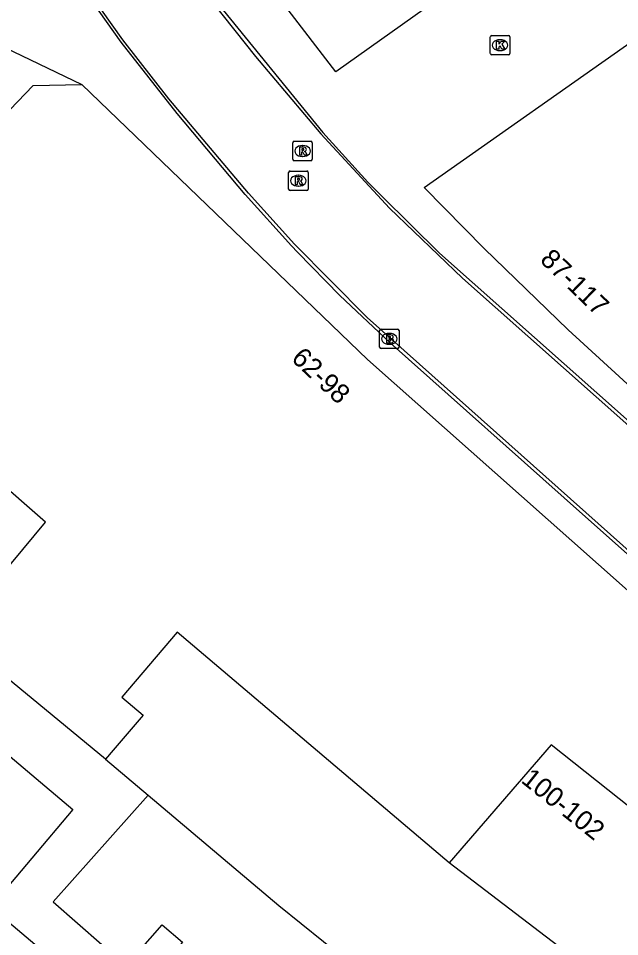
# Model space of a CAD drawing. Extents: x 161087 to 161922, y 382574 to 383873.
# Drawn here: x 161162.7 to 161193.61, y 383299.11 to 383346.31 of the extents above; entities that cross this region are included whole.
import ezdxf

# ---------------------------------------------------------------- set-up
doc = ezdxf.new("R2010")
doc.units = 0
for name, color, linetype in [('IMGEO_Brandkraan', 7, 'Continuous'), ('IMGEO_Kolk', 7, 'Continuous'), ('IMGEO_Lijnafwatering', 7, 'Continuous'), ('IMGEO_Pand', 7, 'Continuous'), ('IMGEO_Pand_nummerreeks', 7, 'Continuous'), ('IMGEO_Rioolput', 7, 'Continuous'), ('IMGEO_Voetgangersgebied_open', 7, 'Continuous')]:
    doc.layers.add(name, color=color, linetype=linetype)

msp = doc.modelspace()

# ---------------------------------------------------------------- linework, layer by layer
at = {"layer": 'IMGEO_Brandkraan'}
for p, q in [((161181.267, 383329.408), (161181.267, 383330.26)), ((161181.342, 383330.334), (161182.194, 383330.334)), ((161182.268, 383330.26), (161182.268, 383329.408)), ((161181.755, 383330.114), (161181.78, 383330.114)), ((161182.194, 383329.334), (161181.342, 383329.334)), ((161181.778, 383329.554), (161181.753, 383329.554))]:
    msp.add_line(p, q, dxfattribs=at)
for points in [[(161181.267, 383329.408), (161181.267, 383330.26)], [(161181.342, 383330.334), (161182.194, 383330.334)], [(161182.268, 383330.26), (161182.268, 383329.408)], [(161181.615, 383330.034), (161181.615, 383329.634), (161181.828, 383329.634)], [(161181.846, 383330.034), (161181.615, 383330.034)], [(161181.794, 383329.953), (161181.74, 383329.953), (161181.74, 383329.877)], [(161181.74, 383329.877), (161181.793, 383329.877)], [(161181.802, 383329.801), (161181.74, 383329.801), (161181.74, 383329.72)], [(161182.194, 383329.334), (161181.342, 383329.334)], [(161181.74, 383329.72), (161181.802, 383329.72)]]:
    msp.add_lwpolyline(points, dxfattribs=at)
for centre, radius, start, end in [((161181.344, 383330.258), 0.0765, 91.552, 178.448), ((161181.344, 383330.258), 0.0765, 91.552, 178.448), ((161182.192, 383330.258), 0.0765, 1.552, 88.448), ((161182.192, 383330.258), 0.0765, 1.552, 88.448), ((161181.795, 383329.915), 0.0379, 267.8285, 90.9355), ((161181.803, 383329.76), 0.0404, 269.8759, 90.5077), ((161181.85, 383329.889), 0.145, 59.4692, 91.5367), ((161181.875, 383329.936), 0.0922, 285.5137, 58.1501), ((161181.88, 383329.744), 0.105, 301.3115, 78.989), ((161181.344, 383329.41), 0.0765, 181.552, 268.448), ((161181.344, 383329.41), 0.0765, 181.552, 268.448), ((161181.834, 383329.885), 0.251, 268.6676, 293.5347), ((161182.192, 383329.41), 0.0765, 271.552, 358.448), ((161182.192, 383329.41), 0.0765, 271.552, 358.448)]:
    msp.add_arc(centre, radius, start, end, dxfattribs=at)
for centre, major_axis, ratio, start_param, end_param in [((161181.754, 383329.834), (-0.387, 0.002), 0.722429, 4.712389, 7.853982), ((161181.779, 383329.834), (-0.39, 0.002), 0.717154, 1.570796, 4.712389)]:
    msp.add_ellipse(centre, major_axis=major_axis, ratio=ratio, start_param=start_param, end_param=end_param, dxfattribs=at)
at = {"layer": 'IMGEO_Kolk'}
for p, q in [((161186.959, 383344.501), (161186.959, 383345.353)), ((161187.034, 383345.427), (161187.886, 383345.427)), ((161187.96, 383345.353), (161187.96, 383344.501)), ((161187.447, 383345.207), (161187.472, 383345.207)), ((161187.886, 383344.427), (161187.034, 383344.427)), ((161187.47, 383344.647), (161187.445, 383344.647))]:
    msp.add_line(p, q, dxfattribs=at)
for points in [[(161186.959, 383344.501), (161186.959, 383345.353)], [(161187.034, 383345.427), (161187.886, 383345.427)], [(161187.96, 383345.353), (161187.96, 383344.501)], [(161187.28, 383345.127), (161187.403, 383345.127), (161187.403, 383344.976), (161187.533, 383345.127), (161187.697, 383345.127), (161187.551, 383344.976), (161187.704, 383344.727), (161187.552, 383344.727), (161187.467, 383344.891), (161187.403, 383344.824), (161187.403, 383344.727), (161187.28, 383344.727), (161187.28, 383345.127)], [(161187.886, 383344.427), (161187.034, 383344.427)]]:
    msp.add_lwpolyline(points, dxfattribs=at)
for centre, start, end in [((161187.036, 383345.351), 91.552, 178.448), ((161187.036, 383345.351), 91.552, 178.448), ((161187.884, 383345.351), 1.552, 88.448), ((161187.884, 383345.351), 1.552, 88.448), ((161187.036, 383344.503), 181.552, 268.448), ((161187.036, 383344.503), 181.552, 268.448), ((161187.884, 383344.503), 271.552, 358.448), ((161187.884, 383344.503), 271.552, 358.448)]:
    msp.add_arc(centre, 0.0765, start, end, dxfattribs=at)
for centre, major_axis, ratio, start_param, end_param in [((161187.446, 383344.927), (-0.387, 0.002), 0.722429, 4.712389, 7.853982), ((161187.471, 383344.927), (-0.39, 0.002), 0.717154, 1.570796, 4.712389)]:
    msp.add_ellipse(centre, major_axis=major_axis, ratio=ratio, start_param=start_param, end_param=end_param, dxfattribs=at)
at = {"layer": 'IMGEO_Lijnafwatering'}
for points in [[(161169.336, 383352.194), (161170.786, 383350.004), (161172.858, 383347.181), (161178.355, 383340.444), (161180.665, 383337.883), (161181.381, 383337.174)], [(161177.057, 383334.286), (161176.737, 383334.613), (161174.352, 383337.257), (161170.862, 383341.421), (161167.982, 383345.086), (161165.257, 383348.941), (161164.689, 383349.834)], [(161181.381, 383337.174), (161184.339, 383334.242), (161195.644, 383324.209)], [(161191.698, 383320.83), (161181.81, 383329.622), (161179.225, 383332.066), (161177.057, 383334.286)], [(161206.563, 383307.612), (161191.698, 383320.83)]]:
    msp.add_lwpolyline(points, dxfattribs=at)
at = {"layer": 'IMGEO_Pand'}
for points in [[(161190.477, 383351.704), (161179.021, 383343.554), (161171.159, 383353.793), (161169.837, 383356.018), (161168.737, 383358.257), (161167.679, 383361.087), (161167.021, 383363.539), (161166.588, 383366.045), (161166.359, 383369.079), (161166.413, 383371.664), (161166.697, 383374.139), (161167.358, 383377.079), (161191.383, 383468.603)], [(161216.207, 383315.883), (161215.752, 383316.357), (161214.691, 383315.791), (161213.343, 383315.363), (161212.274, 383315.225), (161210.843, 383315.3), (161209.813, 383315.542), (161208.808, 383315.943), (161207.486, 383316.594), (161206.214, 383317.343), (161204.425, 383318.638), (161199.971, 383322.288), (161195.397, 383326.239), (161190.957, 383330.305), (161186.641, 383334.476), (161183.556, 383337.621), (161194.717, 383345.454)], [(161151.494, 383321.17), (161147.415, 383324.537), (161151.946, 383330.508), (161152.177, 383330.332), (161153.092, 383331.385), (161152.76, 383331.703), (161163.467, 383342.861), (161165.961, 383342.908)], [(161165.961, 383342.908), (161180.652, 383328.776), (161205.761, 383306.486), (161206.057, 383306.043), (161206.166, 383305.635), (161206.123, 383305.078), (161205.895, 383304.607)], [(161167.185, 383308.226), (161159.33, 383314.694), (161164.095, 383320.413), (161161.313, 383322.825), (161156.374, 383317.128), (161152.859, 383320.023), (161151.494, 383321.17)], [(161149.625, 383319.064), (161165.502, 383305.649), (161161.277, 383300.648), (161162.431, 383299.673), (161169.587, 383293.626), (161168.405, 383292.227), (161172.743, 383288.452), (161173.986, 383289.923)], [(161184.851, 383302.91), (161170.872, 383314.761), (161168.028, 383311.429), (161169.122, 383310.495), (161167.583, 383308.693), (161167.185, 383308.226)], [(161201.65, 383299.789), (161190.093, 383308.977), (161184.851, 383302.91)], [(161167.185, 383308.226), (161169.365, 383306.387)], [(161169.365, 383306.387), (161164.484, 383300.903), (161168.251, 383297.615), (161170.086, 383299.717), (161171.14, 383298.826), (161169.016, 383296.313), (161172.011, 383293.783), (161171.255, 383292.889), (161172.187, 383292.102), (161171.856, 383291.709), (161173.986, 383289.923)], [(161169.365, 383306.387), (161176.09, 383300.716), (161180.68, 383297.011), (161191.255, 383287.61)], [(161196.663, 383293.883), (161184.851, 383302.91)]]:
    msp.add_lwpolyline(points, dxfattribs=at)
at = {"layer": 'IMGEO_Rioolput'}
for p, q in [((161176.809, 383339.063), (161176.809, 383339.915)), ((161176.884, 383339.989), (161177.736, 383339.989)), ((161177.297, 383339.769), (161177.322, 383339.769)), ((161177.81, 383339.915), (161177.81, 383339.063)), ((161177.32, 383339.209), (161177.295, 383339.209)), ((161177.736, 383338.989), (161176.884, 383338.989)), ((161176.594, 383337.535), (161176.594, 383338.387)), ((161176.669, 383338.461), (161177.521, 383338.461)), ((161177.082, 383338.241), (161177.107, 383338.241)), ((161177.595, 383338.387), (161177.595, 383337.535)), ((161177.521, 383337.461), (161176.669, 383337.461)), ((161177.105, 383337.681), (161177.08, 383337.681))]:
    msp.add_line(p, q, dxfattribs=at)
for points in [[(161176.809, 383339.063), (161176.809, 383339.915)], [(161176.884, 383339.989), (161177.736, 383339.989)], [(161177.398, 383339.687), (161177.146, 383339.689), (161177.146, 383339.289)], [(161177.81, 383339.915), (161177.81, 383339.063)], [(161177.146, 383339.289), (161177.27, 383339.289), (161177.27, 383339.451), (161177.281, 383339.451)], [(161177.324, 383339.608), (161177.27, 383339.608), (161177.27, 383339.527)], [(161177.27, 383339.527), (161177.322, 383339.527)], [(161177.328, 383339.422), (161177.399, 383339.289), (161177.539, 383339.289), (161177.474, 383339.415)], [(161177.736, 383338.989), (161176.884, 383338.989)], [(161176.594, 383337.535), (161176.594, 383338.387)], [(161176.669, 383338.461), (161177.521, 383338.461)], [(161177.595, 383338.387), (161177.595, 383337.535)], [(161177.183, 383338.159), (161176.931, 383338.161), (161176.931, 383337.761)], [(161176.931, 383337.761), (161177.055, 383337.761), (161177.055, 383337.923), (161177.066, 383337.923)], [(161177.109, 383338.08), (161177.055, 383338.08), (161177.055, 383337.999)], [(161177.055, 383337.999), (161177.107, 383337.999)], [(161177.113, 383337.894), (161177.184, 383337.761), (161177.324, 383337.761), (161177.259, 383337.887)], [(161177.521, 383337.461), (161176.669, 383337.461)]]:
    msp.add_lwpolyline(points, dxfattribs=at)
for centre, radius, start, end in [((161176.886, 383339.913), 0.0765, 91.552, 178.448), ((161176.886, 383339.913), 0.0765, 91.552, 178.448), ((161177.397, 383339.577), 0.109, 350.3612, 89.416), ((161177.734, 383339.913), 0.0765, 1.552, 88.448), ((161177.734, 383339.913), 0.0765, 1.552, 88.448), ((161177.28, 383339.398), 0.0533, 26.0293, 88.6989), ((161177.306, 383339.716), 0.19, 274.7715, 282.9687), ((161177.33, 383339.512), 0.0964, 77.0061, 93.1865), ((161177.344, 383339.569), 0.0378, 276.6634, 79.6772), ((161177.395, 383339.577), 0.112, 277.5842, 350.9817), ((161177.379, 383339.362), 0.108, 29.5134, 73.7905), ((161176.886, 383339.065), 0.0765, 181.552, 268.448), ((161176.886, 383339.065), 0.0765, 181.552, 268.448), ((161177.734, 383339.065), 0.0765, 271.552, 358.448), ((161177.734, 383339.065), 0.0765, 271.552, 358.448), ((161176.671, 383338.385), 0.0765, 91.552, 178.448), ((161176.671, 383338.385), 0.0765, 91.552, 178.448), ((161177.519, 383338.385), 0.0765, 1.552, 88.448), ((161177.519, 383338.385), 0.0765, 1.552, 88.448), ((161177.065, 383337.87), 0.0533, 26.0293, 88.6989), ((161177.091, 383338.188), 0.19, 274.7715, 282.9687), ((161177.115, 383337.984), 0.0964, 77.0061, 93.1865), ((161177.129, 383338.041), 0.0378, 276.6634, 79.6772), ((161177.182, 383338.049), 0.109, 350.3612, 89.416), ((161177.18, 383338.049), 0.112, 277.5842, 350.9817), ((161177.164, 383337.834), 0.108, 29.5134, 73.7905), ((161176.671, 383337.537), 0.0765, 181.552, 268.448), ((161176.671, 383337.537), 0.0765, 181.552, 268.448), ((161177.519, 383337.537), 0.0765, 271.552, 358.448), ((161177.519, 383337.537), 0.0765, 271.552, 358.448)]:
    msp.add_arc(centre, radius, start, end, dxfattribs=at)
for centre, major_axis, ratio, start_param, end_param in [((161177.296, 383339.489), (-0.387, 0.002), 0.722429, 4.712389, 7.853982), ((161177.321, 383339.489), (-0.39, 0.002), 0.717154, 1.570796, 4.712389), ((161177.081, 383337.961), (-0.387, 0.002), 0.722429, 4.712389, 7.853982), ((161177.106, 383337.961), (-0.39, 0.002), 0.717154, 1.570796, 4.712389)]:
    msp.add_ellipse(centre, major_axis=major_axis, ratio=ratio, start_param=start_param, end_param=end_param, dxfattribs=at)
at = {"layer": 'IMGEO_Voetgangersgebied_open'}
for points in [[(161172.704, 383347.099), (161174.894, 383344.353), (161178.253, 383340.363), (161181.784, 383336.552), (161185.534, 383332.959), (161209.498, 383311.67), (161206.276, 383308.055), (161180.636, 383330.931), (161176.902, 383334.697), (161174.529, 383337.32), (161170.441, 383342.173), (161168.079, 383345.195), (161165.419, 383348.959)], [(161158.897, 383346.301), (161165.961, 383342.908)]]:
    msp.add_lwpolyline(points, dxfattribs=at)

# ---------------------------------------------------------------- texts
at = {"layer": 'IMGEO_Pand_nummerreeks'}
for s, rotation, p in [('87-117', 315.9788, (161189.462, 383333.836)), ('62-98', 316.6603, (161176.677, 383328.765)), ('100-102', 321.3139, (161188.485, 383307.076))]:
    msp.add_text(s, height=1, rotation=rotation, dxfattribs=at).set_placement(p)

doc.saveas('drawing.dxf')
